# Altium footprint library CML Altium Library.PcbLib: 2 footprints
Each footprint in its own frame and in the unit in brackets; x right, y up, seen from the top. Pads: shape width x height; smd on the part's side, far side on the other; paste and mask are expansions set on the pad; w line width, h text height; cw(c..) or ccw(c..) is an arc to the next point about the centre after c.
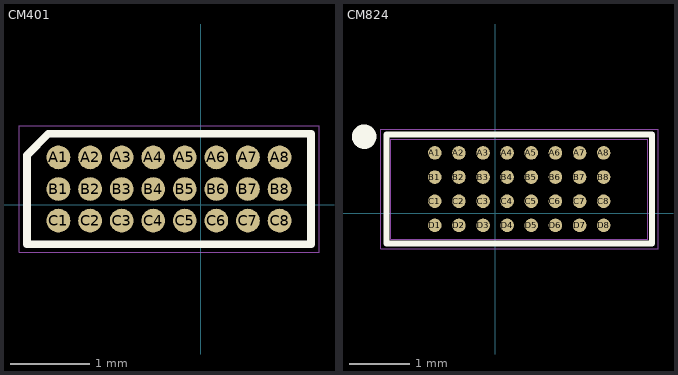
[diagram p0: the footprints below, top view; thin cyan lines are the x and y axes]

## CM401 [mm] "BGA footprint for CM401"
height 0.3
pads (24):
  round 0.3 smd mask+0.02: A1(-1.8,0.6) A2(-1.4,0.6) A3(-1,0.6) A4(-0.6,0.6) A5(-0.2,0.6) A6(0.2,0.6) A7(0.6,0.6) A8(1,0.6) B1(-1.8,0.2) B2(-1.4,0.2) B3(-1,0.2) B4(-0.6,0.2) B5(-0.2,0.2) B6(0.2,0.2) B7(0.6,0.2) B8(1,0.2) C1(-1.8,-0.2) C2(-1.4,-0.2) C3(-1,-0.2) C4(-0.6,-0.2) C5(-0.2,-0.2) C6(0.2,-0.2) C7(0.6,-0.2) C8(1,-0.2)
Top Overlay:
  lines w0.1: -2.201,-0.5 1.4,-0.5 1.4,0.9 -1.928,0.9 -2.2,0.628 ; -2.2,-0.5 -2.2,0.628 ; -2.2,0.609 -2.2,0.628
Assembly Layer:
  lines w0.01: -2.3,-0.6 1.5,-0.6 1.5,1 -2.3,1 -2.3,-0.6
  text ".Designator" at -1.7,0.09 h0.3
3D body: height 0.3, standoff 0, extent -2.095,-0.408 1.285,0.812

## CM824 [mm] "BGA footprint for CM824"
height 0.3
pads (32):
  round 0.225 smd paste+0.025 mask+0.032: A1(-1,1) A2(-0.6,1) A3(-0.2,1) A4(0.2,1) A5(0.6,1) A6(1,1) A7(1.4,1) A8(1.8,1) B1(-1,0.6) B2(-0.6,0.6) B3(-0.2,0.6) B4(0.2,0.6) B5(0.6,0.6) B6(1,0.6) B7(1.4,0.6) B8(1.8,0.6) C1(-1,0.2) C2(-0.6,0.2) C3(-0.2,0.2) C4(0.2,0.2) C5(0.6,0.2) C6(1,0.2) C7(1.4,0.2) C8(1.8,0.2) D1(-1,-0.2) D2(-0.6,-0.2) D3(-0.2,-0.2) D4(0.2,-0.2) D5(0.6,-0.2) D6(1,-0.2) D7(1.4,-0.2) D8(1.8,-0.2)
Top Overlay:
  circle w0.2: c-2.17,1.27 r0.103
  lines w0.1: -1.8,-0.501 -1.8,1.308 2.6,1.308 2.6,-0.501 -1.8,-0.501
Assembly Layer:
  lines w0.01: -1.9,-0.591 2.701,-0.591 2.701,1.395 -1.9,1.395 -1.9,-0.591
  text ".Designator" at -1.016,0.381 h0.3
3D Model:
  lines w0.01: -1.731,-0.43 2.529,-0.43 2.529,1.23 -1.731,1.23 -1.731,-0.43
3D body: height 0.3, standoff 0, extent -1.731,-0.43 2.529,1.23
